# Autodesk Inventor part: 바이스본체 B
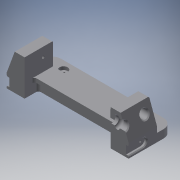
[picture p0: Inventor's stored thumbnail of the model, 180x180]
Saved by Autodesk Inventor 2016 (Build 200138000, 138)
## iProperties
Created: 2017-04
Part Number: 바이스본체 B
Material: 알루미늄 6061
Document SubType Name: Modeling
Designer: mduedu
Density: 2.71 g/cm^3
Appearance: 기본값
Mass: 324.113 g
Surface Area: 275.971 cm^2
Volume: 119.599 cm^3
Author: mduedu
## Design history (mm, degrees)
sketch "스케치1"
  geometry: L1 (-75, 0)-(75, 0); L2 (-75, 0)-(-75, 17); L3 (-53, 17)-(53, 17); L4 (75, 17)-(75, 0); L5 (-75, 17)-(-65.173, 44); L6 (-65.173, 44)-(-53, 44); L7 (-53, 44)-(-53, 17); L8 (0, 0)-(0, 17); L9 (75, 17)-(65.173, 44); L10 (65.173, 44)-(53, 44); L11 (53, 44)-(53, 17); 1 further point
  constraints: 22 end point, 4 perpendicular, 2 horizontal alignment, 2 midpoint, 2 symmetric about line, 1 coincident, 1 collinear, 1 horizontal, 1 vertical
  dimensions: "d0" = 150 distance of L1.start L1.end; "d1" = 17 distance of L1.start L2.end; "d2" = 27 distance of L3.start L6.end; "d3" = 22 distance of L3.start L2.end; "d4" = 70 deg angle of L3 L5; "d54" = 20 deg angle of L9 L4
extrude "돌출1" new body sketch "스케치1" stored distance "d5" = 70; taper "d6" = 0 deg
sketch "스케치2"
  geometry: L1 (0, 70)-(106, 70) reference; L2 (106, 70)-(106, 0) reference; L3 (106, 0)-(0, 0) reference; L4 (0, 47)-(106, 47); L5 (106, 47)-(106, 23); L6 (106, 23)-(0, 23); L7 (0, 23)-(0, 47); L8 (0, 70)-(0, 0) reference; 2 further points
  constraints: 8 end point, 2 parallel, 2 point on line, 1 horizontal, 1 horizontal alignment, 1 midpoint, 1 perpendicular
  dimensions: "d7" = 24 distance between parallel lines of L6 L4
extrude "돌출2" cut sketch "스케치2" stored distance "d9" = 70; taper "d10" = 0 deg
sketch "스케치3"
  geometry: L1 (22, -23)-(128, -23) reference; L2 (128, -47)-(22, -47) reference; L3 (22, -18)-(128, -18); L4 (128, -52)-(22, -52); L5 (22, -18)-(22, -52); L6 (128, -18)-(128, -52); 1 further point
  constraints: 8 end point, 3 parallel, 2 point on line, 1 perpendicular
  dimensions: "d11" = 5 distance between parallel lines of L3 L1; "d12" = 5 distance between parallel lines of L4 L2
extrude "돌출3" cut sketch "스케치3" distance "d13" = 12; taper "d14" = 0 deg
fillet "모깎기1" dims "d15" = 3, "d16" = 3
sketch "스케치4"
  geometry: L1 (103, 23)-(3, 23) reference; L2 (0, 26)-(0, 0) reference; L3 (106, 0)-(0, 0) reference; L4 (106, 26)-(106, 0) reference; L5 (96, 0)-(90, 0); L6 (90, 0)-(90, 19.5); L7 (96, 19.5)-(96, 0); L8 (90, 19.5)-(96, 19.5); A1 r 3 centre (3, 26) between (0, 26) and (3, 23) reference; A2 r 3 centre (103, 26) between (103, 23) and (106, 26) reference; 1 further point
  constraints: 8 end point, 2 perpendicular, 1 horizontal, 1 parallel, 1 point on line
  dimensions: "d17" = 10 distance between parallel lines of L7 L4; "d18" = 6 distance between parallel lines of L7 L6; "d27" = 3.5 distance between parallel lines of L8 L1
extrude "돌출4" join sketch "스케치4" distance "d19" = 12; taper "d20" = 0 deg
chamfer "모따기1" distance "d21" = 3; stored, may be unused: second distance "d22" = 2, angle "d23" = 45 deg
chamfer "모따기2" distance "d24" = 3; stored, may be unused: second distance "d25" = 2, angle "d26" = 45 deg
sketch "스케치5"
  geometry: L1 (-15.5, 35.8)-(-15.5, -25.8) reference; L2 (19.5, 0)-(0, 0) reference; C1 r 6.5 at (9.5, 15); 1 further point
  constraints: 1 centre point
  dimensions: "d28" = 13 diameter of C1; "d30" = 15 distance from line of C1.centre L2; "d31" = 25 distance from line of C1.centre L1
extrude "돌출5" cut sketch "스케치5" stored distance "d32" = 12; taper "d33" = 0 deg
sketch "스케치6"
  geometry: C1 r 5 at (-10, 15); C2 r 5 at (-60, 15); A1 r 6.5 centre (-10, 15) between (-15.766, 12) and (-4.234, 12) reference; A2 r 6.5 centre (-60, 15) between (-65.766, 12) and (-54.234, 12) reference; 1 further point
  constraints: 2 centre point, 2 coincident
  dimensions: "d34" = 10 diameter of C1; "d35" = 10 diameter of C2 (= d34)
extrude "돌출6" cut sketch "스케치6" stored distance "d36" = 12; taper "d37" = 0 deg
chamfer "모따기3" distance "d38" = 1; stored, may be unused: second distance "d39" = 2, angle "d40" = 45 deg
chamfer "모따기4" distance "d41" = 1; stored, may be unused: second distance "d42" = 2, angle "d43" = 45 deg
sketch "스케치7"
  geometry: L1 (-35, 35.8)-(-35, -25.8) reference; L2 (-70, 0)-(0, 0) reference; C1 r 5 at (-35, 15); 1 further point
  constraints: 1 centre point, 1 point on line
  dimensions: "d44" = 10 diameter of C1; "d45" = 15 distance from line of C1.centre L2
extrude "돌출7" cut sketch "스케치7" stored distance "d46" = 12; taper "d47" = 0 deg
chamfer "모따기5" distance "d48" = 1; stored, may be unused: second distance "d49" = 2, angle "d50" = 45 deg
node "작업축1"
sketch "스케치8"
  geometry: L1 (-105, 32)-(105, 32) reference; L2 (58, 32)-(64, 32); L3 (64, 32)-(64, 40); L4 (64, 40)-(58, 40); L5 (58, 40)-(58, 32); L6 (53, 38)-(53, 26) reference; 1 further point
  constraints: 8 end point, 2 parallel, 1 horizontal, 1 perpendicular, 1 point on line
  dimensions: "d51" = 5 distance from line of L6 L2.start; "d52" = 6 distance of L3.end L4.end; "d53" = 16 diameter of L4 L1
revolve "회전1" sketch "스케치8" stored, may be unused: angle "d55" = 90 deg
fillet "모깎기2"
chamfer "모따기6" distance "d56" = 1; stored, may be unused: second distance "d57" = 2, angle "d58" = 45 deg
sketch "스케치9"
  geometry: L1 (17.5, 3)-(52.5, 3); L2 (52.5, 13)-(17.5, 13); L3 (70, 0)-(0, 0) reference; L4 (17.5, 8)-(52.5, 8); A1 r 5 centre (17.5, 8) between (17.5, 13) and (17.5, 3); A2 r 5 centre (52.5, 8) between (52.5, 3) and (52.5, 13); 3 further points
  constraints: 6 end point, 4 point on circle, 3 tangent, 2 centre point, 2 midpoint, 2 parallel, 1 horizontal, 1 vertical alignment
  dimensions: "d59" = 35 distance of L4.start L4.end; "d61" = 5 radius of A2; "d62" = 8 distance between parallel lines of L3 L4
extrude "돌출8" cut sketch "스케치9" distance "d63" = 3; taper "d64" = 0 deg
chamfer "모따기7" distance "d65" = 1; stored, may be unused: second distance "d66" = 2, angle "d67" = 45 deg
chamfer "모따기8" distance "d68" = 1; stored, may be unused: second distance "d69" = 2, angle "d70" = 45 deg
feature "분할1"
sketch "스케치10"
  geometry: A1 r 5 centre (0, 0) between (0, 5) and (0, -5) reference; 1 further point
  constraints: 1 coincident
hole "구멍1" sketch "스케치10" at (0, 0) diameter "d71" = 2.459; stored, may be unused: countersink angle "d75" = 90 deg, drill point angle "d77" = 120 deg; dims "d72" = 4.5, "d73" = 4, "d74" = 2, "d76" = 6
sketch "스케치11"
  geometry: L1 (0, 0)-(0, 27) reference; L2 (0, 27)-(-35, 27) reference; 2 further points
  dimensions: "d78" = 12 distance from line of point (-12, 15.5) L1; "d79" = 11.5 distance from line of point (-12, 15.5) L2
hole "구멍2" sketch "스케치11" at (-12, 15.5) diameter "d80" = 3.242; stored, may be unused: countersink angle "d84" = 90 deg, drill point angle "d86" = 120 deg; dims "d81" = 8, "d82" = 4, "d83" = 2, "d85" = 10
sketch "스케치12"
  geometry: L1 (-75, -35)-(-75, 0) reference; L2 (75, -35)-(75, 0) reference; L3 (75, -35)-(-75, -35); L4 (-75, -35)-(-75, -55); L5 (-75, -55)-(75, -55); L6 (75, -55)-(75, -35); 1 further point
  constraints: 8 end point, 2 parallel, 1 horizontal, 1 perpendicular, 1 point on line
  dimensions: "d87" = 20 distance of L3.end L4.end; "d89" = 150 distance of L4.end L5.end (derived)
extrude "돌출9" join sketch "스케치12" distance "d90" = 10; taper "d91" = 0 deg
sketch "스케치13"
  geometry: L1 (-75, 55)-(-75, 35) reference; L2 (75, 35)-(75, 55) reference; L3 (-75, 45)-(75, 45); 3 further points
  constraints: 2 end point, 2 midpoint, 2 point on line
  dimensions: "d92" = 50 horizontal distance of point (-50, 45) point (0, 0); "d93" = 100 distance of point (50, 45) point (-50, 45)
fillet "모깎기3" dims "d94" = 12
chamfer "모따기9" distance "d95" = 1; stored, may be unused: second distance "d96" = 2, angle "d97" = 45 deg
hole "구멍3" sketch "스케치13" diameter "d98" = 4.134; stored, may be unused: countersink angle "d102" = 90 deg, drill point angle "d104" = 118 deg; dims "d99" = 6, "d100" = 10, "d101" = 4, "d103" = 8
node "솔리드1"
mirror "대칭1"
mirror "대칭2"
mirror "대칭3"
mirror "대칭4"
node "투영된 루프1"
